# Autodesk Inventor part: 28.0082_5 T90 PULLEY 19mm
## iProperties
Created: 2006-12
Document SubType Name: Modeling
Designer: Andy Moles
Part Number: 28.0082_5 T90 PULLEY 19mm
Material: Aluminum-6061
Density: 2.71 g/cm^3
Author: Andy Moles
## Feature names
1. Extrusion1
2. Extrusion3
3. Extrusion4
4. Extrusion6
5. Mirror1
6. Extrusion7
7. Chamfer1
